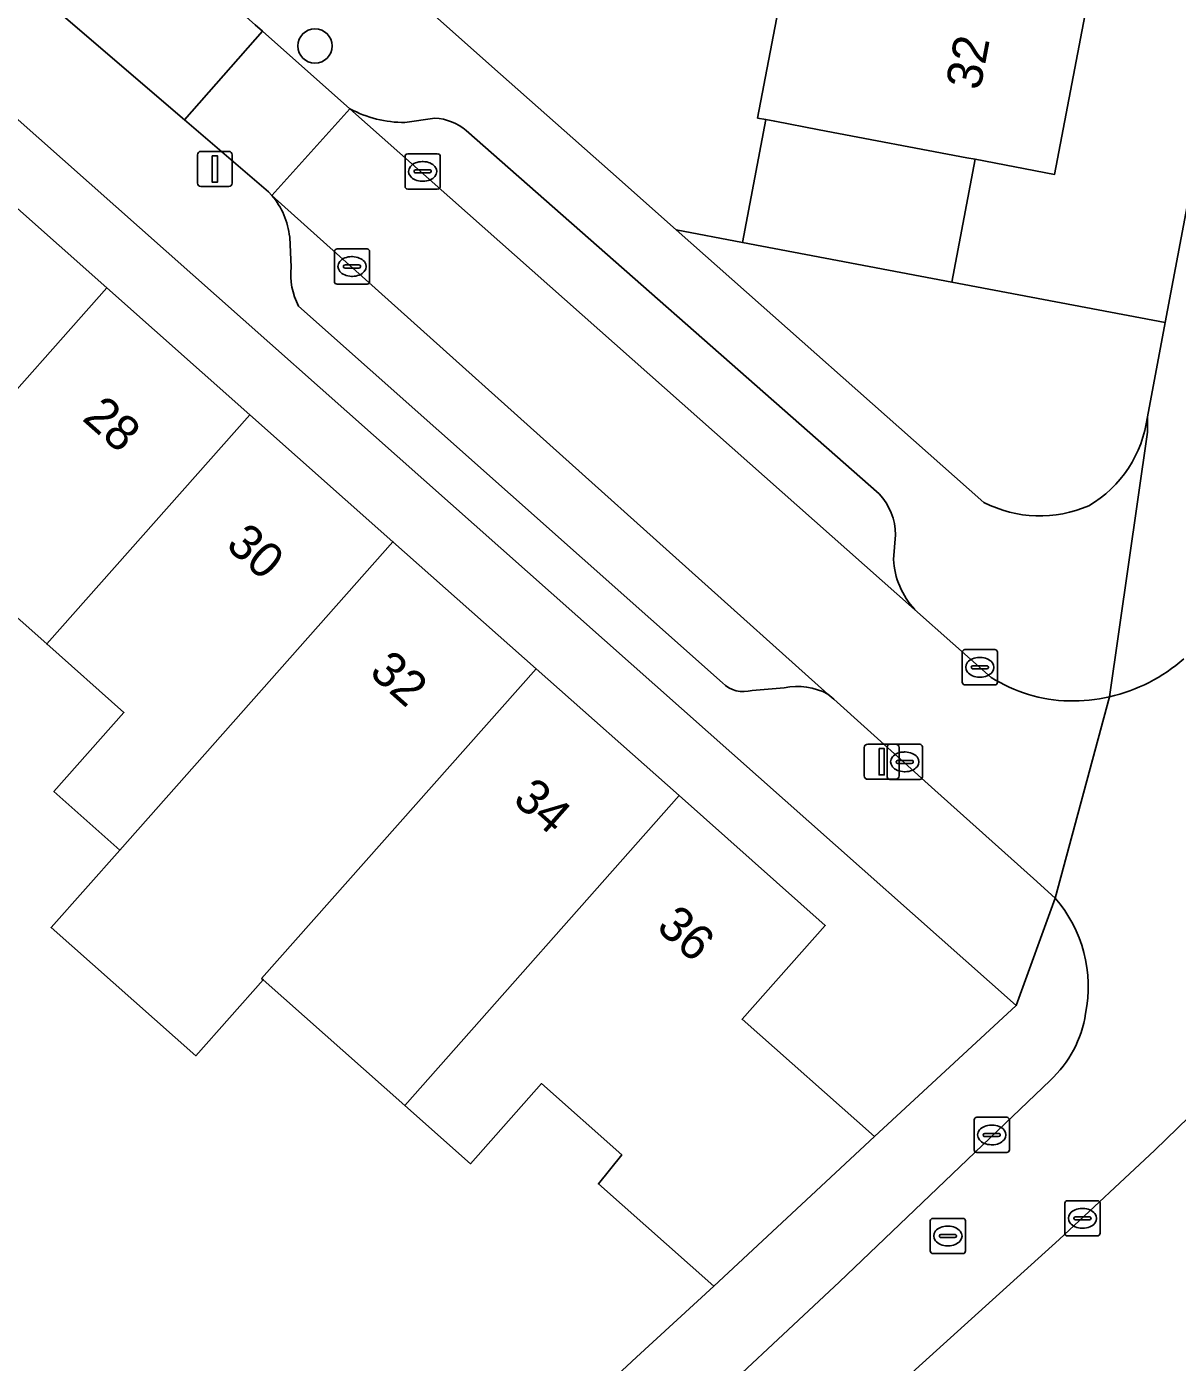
# Model space of a CAD drawing. Extents: x 163147 to 163550, y 380933 to 381639.
# Drawn here: x 163402.15 to 163434.83, y 381022.1 to 381060.03 of the extents above; entities that cross this region are included whole.
import ezdxf

# ---------------------------------------------------------------- set-up
doc = ezdxf.new("R2010")
doc.units = 0
for name, color, linetype in [('IMGEO_Boom', 7, 'Continuous'), ('IMGEO_Erf', 7, 'Continuous'), ('IMGEO_Groenvoorziening', 7, 'Continuous'), ('IMGEO_Kolk', 7, 'Continuous'), ('IMGEO_Lichtmast', 7, 'Continuous'), ('IMGEO_Muur', 7, 'Continuous'), ('IMGEO_Pand', 7, 'Continuous'), ('IMGEO_Pand_nummerreeks', 7, 'Continuous'), ('IMGEO_Parkeervlak_open', 7, 'Continuous'), ('IMGEO_Rijbaan_lokaal_open', 7, 'Continuous'), ('IMGEO_Rioolput', 7, 'Continuous'), ('IMGEO_Voetpad_open', 7, 'Continuous')]:
    doc.layers.add(name, color=color, linetype=linetype)

msp = doc.modelspace()

# ---------------------------------------------------------------- linework, layer by layer
at = {"layer": 'IMGEO_Boom'}
msp.add_circle((163410.34, 381059.48), 0.489, dxfattribs=at)
at = {"layer": 'IMGEO_Erf'}
for points in [[(163380.041, 381074.245), (163384.106, 381070.638), (163388.17, 381067.033), (163392.234, 381063.427), (163396.298, 381059.822), (163400.361, 381056.217), (163404.425, 381052.611), (163408.489, 381049.006), (163412.553, 381045.4), (163416.617, 381041.795), (163420.681, 381038.189), (163424.834, 381034.505), (163422.47, 381031.841), (163426.228, 381028.508), (163430.25, 381032.233), (163348.313, 381104.939)], [(163435.463, 381077.499), (163434.445, 381072.144), (163433.428, 381066.79), (163432.41, 381061.436), (163431.345, 381055.832), (163429.088, 381056.261), (163428.425, 381052.773), (163434.486, 381051.622), (163441.105, 381086.644)], [(163413.645, 381060.421), (163415.366, 381058.896), (163418.735, 381055.912), (163420.6, 381054.259), (163422.486, 381053.901), (163423.149, 381057.389), (163422.91, 381057.434), (163423.49, 381060.487)], [(163405.039, 381008.81), (163419.469, 381022.239), (163421.663, 381024.258), (163418.388, 381027.163), (163419.053, 381027.989), (163416.776, 381030.012), (163414.756, 381027.733), (163412.887, 381029.393), (163408.87, 381032.959), (163406.956, 381030.801), (163402.846, 381034.445), (163404.794, 381036.643), (163402.925, 381038.304), (163404.915, 381040.549), (163402.722, 381042.497), (163400.529, 381044.445)]]:
    msp.add_lwpolyline(points, dxfattribs=at)
at = {"layer": 'IMGEO_Groenvoorziening'}
for points in [[(163434.486, 381051.622), (163428.425, 381052.773), (163422.486, 381053.901), (163420.6, 381054.259), (163429.339, 381046.517)], [(163433.981, 381048.948), (163434.486, 381051.622)]]:
    msp.add_lwpolyline(points, dxfattribs=at)
for centre, radius, start, end in [((163430.589, 381049.373), 3.418, 300.322, 352.8651), ((163430.928, 381049.622), 3.488, 242.9053, 293.4379)]:
    msp.add_arc(centre, radius, start, end, dxfattribs=at)
at = {"layer": 'IMGEO_Kolk'}
for p, q in [((163412.897, 381055.49), (163412.897, 381056.342)), ((163412.972, 381056.416), (163413.824, 381056.416)), ((163413.898, 381056.342), (163413.898, 381055.49)), ((163413.156, 381055.91), (163413.156, 381055.922)), ((163413.594, 381055.873), (163413.196, 381055.873)), ((163413.199, 381055.959), (163413.597, 381055.959)), ((163413.385, 381056.196), (163413.41, 381056.196)), ((163413.64, 381055.922), (163413.64, 381055.91)), ((163413.408, 381055.636), (163413.383, 381055.636)), ((163413.824, 381055.416), (163412.972, 381055.416)), ((163410.891, 381052.791), (163410.891, 381053.643)), ((163410.966, 381053.717), (163411.818, 381053.717)), ((163411.892, 381053.643), (163411.892, 381052.791)), ((163411.15, 381053.211), (163411.15, 381053.223)), ((163411.193, 381053.26), (163411.591, 381053.26)), ((163411.379, 381053.497), (163411.404, 381053.497)), ((163411.634, 381053.223), (163411.634, 381053.211)), ((163411.588, 381053.174), (163411.19, 381053.174)), ((163411.402, 381052.937), (163411.377, 381052.937)), ((163411.818, 381052.717), (163410.966, 381052.717)), ((163428.722, 381041.409), (163428.722, 381042.261)), ((163428.797, 381042.335), (163429.649, 381042.335)), ((163429.723, 381042.261), (163429.723, 381041.409)), ((163428.981, 381041.829), (163428.981, 381041.841)), ((163429.024, 381041.878), (163429.422, 381041.878)), ((163429.21, 381042.115), (163429.235, 381042.115)), ((163429.465, 381041.841), (163429.465, 381041.829)), ((163429.419, 381041.792), (163429.021, 381041.792)), ((163429.233, 381041.555), (163429.208, 381041.555)), ((163429.649, 381041.335), (163428.797, 381041.335)), ((163426.589, 381038.723), (163426.589, 381039.575)), ((163426.664, 381039.649), (163427.516, 381039.649)), ((163427.59, 381039.575), (163427.59, 381038.723)), ((163426.891, 381039.192), (163427.289, 381039.192)), ((163427.077, 381039.429), (163427.102, 381039.429)), ((163426.848, 381039.143), (163426.848, 381039.155)), ((163427.286, 381039.106), (163426.888, 381039.106)), ((163427.1, 381038.869), (163427.075, 381038.869)), ((163427.332, 381039.155), (163427.332, 381039.143)), ((163427.516, 381038.649), (163426.664, 381038.649)), ((163429.06, 381028.128), (163429.06, 381028.98)), ((163429.135, 381029.054), (163429.987, 381029.054)), ((163430.061, 381028.98), (163430.061, 381028.128)), ((163429.319, 381028.548), (163429.319, 381028.56)), ((163429.362, 381028.597), (163429.76, 381028.597)), ((163429.548, 381028.834), (163429.573, 381028.834)), ((163429.803, 381028.56), (163429.803, 381028.548)), ((163429.757, 381028.511), (163429.359, 381028.511)), ((163429.571, 381028.274), (163429.546, 381028.274)), ((163429.987, 381028.054), (163429.135, 381028.054)), ((163431.712, 381026.685), (163432.564, 381026.685)), ((163431.637, 381025.759), (163431.637, 381026.611)), ((163432.125, 381026.465), (163432.15, 381026.465)), ((163432.638, 381026.611), (163432.638, 381025.759)), ((163431.896, 381026.179), (163431.896, 381026.191)), ((163432.334, 381026.142), (163431.936, 381026.142)), ((163431.939, 381026.228), (163432.337, 381026.228)), ((163432.148, 381025.905), (163432.123, 381025.905)), ((163432.38, 381026.191), (163432.38, 381026.179)), ((163432.564, 381025.685), (163431.712, 381025.685))]:
    msp.add_line(p, q, dxfattribs=at)
for points in [[(163412.897, 381055.49), (163412.897, 381056.342)], [(163412.972, 381056.416), (163413.824, 381056.416)], [(163413.898, 381056.342), (163413.898, 381055.49)], [(163413.824, 381055.416), (163412.972, 381055.416)], [(163410.891, 381052.791), (163410.891, 381053.643)], [(163410.966, 381053.717), (163411.818, 381053.717)], [(163411.892, 381053.643), (163411.892, 381052.791)], [(163411.818, 381052.717), (163410.966, 381052.717)], [(163428.722, 381041.409), (163428.722, 381042.261)], [(163428.797, 381042.335), (163429.649, 381042.335)], [(163429.723, 381042.261), (163429.723, 381041.409)], [(163429.649, 381041.335), (163428.797, 381041.335)], [(163426.589, 381038.723), (163426.589, 381039.575)], [(163426.664, 381039.649), (163427.516, 381039.649)], [(163427.59, 381039.575), (163427.59, 381038.723)], [(163427.516, 381038.649), (163426.664, 381038.649)], [(163429.06, 381028.128), (163429.06, 381028.98)], [(163429.135, 381029.054), (163429.987, 381029.054)], [(163430.061, 381028.98), (163430.061, 381028.128)], [(163429.987, 381028.054), (163429.135, 381028.054)], [(163431.712, 381026.685), (163432.564, 381026.685)], [(163431.637, 381025.759), (163431.637, 381026.611)], [(163432.638, 381026.611), (163432.638, 381025.759)], [(163432.564, 381025.685), (163431.712, 381025.685)]]:
    msp.add_lwpolyline(points, dxfattribs=at)
for centre, radius, start, end in [((163412.974, 381056.34), 0.0765, 91.552, 178.448), ((163412.974, 381056.34), 0.0765, 91.552, 178.448), ((163413.822, 381056.34), 0.0765, 1.552, 88.448), ((163413.822, 381056.34), 0.0765, 1.552, 88.448), ((163413.196, 381055.919), 0.0403, 85.8775, 175.7526), ((163413.193, 381055.909), 0.0366, 178.938, 274.7102), ((163413.597, 381055.916), 0.043, 264.8664, 352.4533), ((163413.601, 381055.921), 0.0386, 1.7309, 96.639), ((163412.974, 381055.492), 0.0765, 181.552, 268.448), ((163412.974, 381055.492), 0.0765, 181.552, 268.448), ((163413.822, 381055.492), 0.0765, 271.552, 358.448), ((163413.822, 381055.492), 0.0765, 271.552, 358.448), ((163410.968, 381053.641), 0.0765, 91.552, 178.448), ((163410.968, 381053.641), 0.0765, 91.552, 178.448), ((163411.816, 381053.641), 0.0765, 1.552, 88.448), ((163411.816, 381053.641), 0.0765, 1.552, 88.448), ((163411.19, 381053.22), 0.0403, 85.8775, 175.7526), ((163411.187, 381053.21), 0.0366, 178.938, 274.7102), ((163411.591, 381053.217), 0.043, 264.8664, 352.4533), ((163411.595, 381053.222), 0.0386, 1.7309, 96.639), ((163410.968, 381052.793), 0.0765, 181.552, 268.448), ((163410.968, 381052.793), 0.0765, 181.552, 268.448), ((163411.816, 381052.793), 0.0765, 271.552, 358.448), ((163411.816, 381052.793), 0.0765, 271.552, 358.448), ((163428.799, 381042.259), 0.0765, 91.552, 178.448), ((163428.799, 381042.259), 0.0765, 91.552, 178.448), ((163429.647, 381042.259), 0.0765, 1.552, 88.448), ((163429.647, 381042.259), 0.0765, 1.552, 88.448), ((163429.021, 381041.838), 0.0403, 85.8775, 175.7526), ((163429.426, 381041.84), 0.0386, 1.7309, 96.639), ((163429.018, 381041.828), 0.0366, 178.938, 274.7102), ((163429.422, 381041.835), 0.043, 264.8664, 352.4533), ((163428.799, 381041.411), 0.0765, 181.552, 268.448), ((163428.799, 381041.411), 0.0765, 181.552, 268.448), ((163429.647, 381041.411), 0.0765, 271.552, 358.448), ((163429.647, 381041.411), 0.0765, 271.552, 358.448), ((163426.666, 381039.573), 0.0765, 91.552, 178.448), ((163426.666, 381039.573), 0.0765, 91.552, 178.448), ((163427.514, 381039.573), 0.0765, 1.552, 88.448), ((163427.514, 381039.573), 0.0765, 1.552, 88.448), ((163426.888, 381039.152), 0.0403, 85.8775, 175.7526), ((163427.293, 381039.154), 0.0386, 1.7309, 96.639), ((163426.885, 381039.142), 0.0366, 178.938, 274.7102), ((163427.289, 381039.149), 0.043, 264.8664, 352.4533), ((163426.666, 381038.725), 0.0765, 181.552, 268.448), ((163426.666, 381038.725), 0.0765, 181.552, 268.448), ((163427.514, 381038.725), 0.0765, 271.552, 358.448), ((163427.514, 381038.725), 0.0765, 271.552, 358.448), ((163429.137, 381028.978), 0.0765, 91.552, 178.448), ((163429.137, 381028.978), 0.0765, 91.552, 178.448), ((163429.985, 381028.978), 0.0765, 1.552, 88.448), ((163429.985, 381028.978), 0.0765, 1.552, 88.448), ((163429.359, 381028.557), 0.0403, 85.8775, 175.7526), ((163429.764, 381028.559), 0.0386, 1.7309, 96.639), ((163429.356, 381028.547), 0.0366, 178.938, 274.7102), ((163429.76, 381028.554), 0.043, 264.8664, 352.4533), ((163429.137, 381028.13), 0.0765, 181.552, 268.448), ((163429.137, 381028.13), 0.0765, 181.552, 268.448), ((163429.985, 381028.13), 0.0765, 271.552, 358.448), ((163429.985, 381028.13), 0.0765, 271.552, 358.448), ((163431.714, 381026.609), 0.0765, 91.552, 178.448), ((163431.714, 381026.609), 0.0765, 91.552, 178.448), ((163432.562, 381026.609), 0.0765, 1.552, 88.448), ((163432.562, 381026.609), 0.0765, 1.552, 88.448), ((163431.936, 381026.188), 0.0403, 85.8775, 175.7526), ((163431.933, 381026.178), 0.0366, 178.938, 274.7102), ((163432.337, 381026.185), 0.043, 264.8664, 352.4533), ((163432.341, 381026.19), 0.0386, 1.7309, 96.639), ((163431.714, 381025.761), 0.0765, 181.552, 268.448), ((163431.714, 381025.761), 0.0765, 181.552, 268.448), ((163432.562, 381025.761), 0.0765, 271.552, 358.448), ((163432.562, 381025.761), 0.0765, 271.552, 358.448)]:
    msp.add_arc(centre, radius, start, end, dxfattribs=at)
for centre, major_axis, ratio, start_param, end_param in [((163413.384, 381055.916), (-0.387, 0.002), 0.722429, 4.712389, 7.853982), ((163413.409, 381055.916), (-0.39, 0.002), 0.717154, 1.570796, 4.712389), ((163411.378, 381053.217), (-0.387, 0.002), 0.722429, 4.712389, 7.853982), ((163411.403, 381053.217), (-0.39, 0.002), 0.717154, 1.570796, 4.712389), ((163429.209, 381041.835), (-0.387, 0.002), 0.722429, 4.712389, 7.853982), ((163429.234, 381041.835), (-0.39, 0.002), 0.717154, 1.570796, 4.712389), ((163427.076, 381039.149), (-0.387, 0.002), 0.722429, 4.712389, 7.853982), ((163427.101, 381039.149), (-0.39, 0.002), 0.717154, 1.570796, 4.712389), ((163429.547, 381028.554), (-0.387, 0.002), 0.722429, 4.712389, 7.853982), ((163429.572, 381028.554), (-0.39, 0.002), 0.717154, 1.570796, 4.712389), ((163432.124, 381026.185), (-0.387, 0.002), 0.722429, 4.712389, 7.853982), ((163432.149, 381026.185), (-0.39, 0.002), 0.717154, 1.570796, 4.712389)]:
    msp.add_ellipse(centre, major_axis=major_axis, ratio=ratio, start_param=start_param, end_param=end_param, dxfattribs=at)
at = {"layer": 'IMGEO_Lichtmast'}
for p, q in [((163407, 381055.587), (163407, 381056.387)), ((163407, 381056.387), (163407, 381055.587)), ((163407.1, 381056.487), (163407.89, 381056.487)), ((163407.89, 381056.487), (163407.1, 381056.487)), ((163407.99, 381056.387), (163407.99, 381055.587)), ((163407.99, 381055.587), (163407.99, 381056.387)), ((163407.89, 381055.487), (163407.1, 381055.487)), ((163407.1, 381055.487), (163407.89, 381055.487)), ((163426.039, 381039.653), (163426.829, 381039.653)), ((163426.829, 381039.653), (163426.039, 381039.653)), ((163425.939, 381038.753), (163425.939, 381039.553)), ((163425.939, 381039.553), (163425.939, 381038.753)), ((163426.929, 381039.553), (163426.929, 381038.753)), ((163426.929, 381038.753), (163426.929, 381039.553)), ((163426.829, 381038.653), (163426.039, 381038.653)), ((163426.039, 381038.653), (163426.829, 381038.653))]:
    msp.add_line(p, q, dxfattribs=at)
for points in [[(163407.42, 381056.362), (163407.57, 381056.362), (163407.57, 381055.612), (163407.42, 381055.612), (163407.42, 381056.362)], [(163426.359, 381039.528), (163426.509, 381039.528), (163426.509, 381038.778), (163426.359, 381038.778), (163426.359, 381039.528)]]:
    msp.add_lwpolyline(points, dxfattribs=at)
for centre, start, end in [((163407.1, 381056.387), 90, 180), ((163407.1, 381056.387), 90, 180), ((163407.89, 381056.387), 0, 90), ((163407.89, 381056.387), 360, 90), ((163407.1, 381055.587), 180, 270), ((163407.1, 381055.587), 180, 270), ((163407.89, 381055.587), 270, 0), ((163407.89, 381055.587), 270, 0), ((163426.039, 381039.553), 90, 180), ((163426.039, 381039.553), 90, 180), ((163426.829, 381039.553), 0, 90), ((163426.829, 381039.553), 360, 90), ((163426.039, 381038.753), 180, 270), ((163426.039, 381038.753), 180, 270), ((163426.829, 381038.753), 270, 0), ((163426.829, 381038.753), 270, 0)]:
    msp.add_arc(centre, 0.1, start, end, dxfattribs=at)
at = {"layer": 'IMGEO_Muur'}
for points in [[(163415.366, 381058.896), (163418.735, 381055.912)], [(163419.469, 381022.239), (163421.663, 381024.258)]]:
    msp.add_lwpolyline(points, dxfattribs=at)
at = {"layer": 'IMGEO_Pand'}
for points in [[(163432.41, 381061.436), (163421.267, 381063.548), (163420.61, 381063.673), (163420.127, 381061.126), (163420.81, 381060.996), (163423.49, 381060.487), (163422.91, 381057.434), (163423.149, 381057.389), (163423.398, 381057.341), (163424.655, 381057.103), (163428.856, 381056.305), (163429.088, 381056.261), (163431.345, 381055.832)], [(163429.088, 381056.261), (163428.856, 381056.305), (163424.655, 381057.103), (163423.398, 381057.341), (163423.149, 381057.389), (163422.486, 381053.901), (163428.425, 381052.773)], [(163404.425, 381052.611), (163400.361, 381056.217), (163394.598, 381049.713), (163396.791, 381047.766), (163394.801, 381045.52), (163396.671, 381043.86)], [(163408.489, 381049.006), (163404.425, 381052.611), (163396.671, 381043.86), (163398.539, 381042.2), (163400.529, 381044.445), (163402.722, 381042.497)], [(163408.489, 381049.006), (163402.722, 381042.497), (163404.915, 381040.549), (163402.925, 381038.304), (163404.794, 381036.643), (163412.553, 381045.4)], [(163416.617, 381041.795), (163412.553, 381045.4), (163404.794, 381036.643), (163402.846, 381034.445), (163406.956, 381030.801), (163408.87, 381032.959), (163408.824, 381032.999)], [(163420.681, 381038.189), (163416.617, 381041.795), (163408.824, 381032.999), (163408.87, 381032.959), (163412.887, 381029.393)], [(163412.887, 381029.393), (163414.756, 381027.733), (163416.776, 381030.012), (163419.053, 381027.989), (163418.388, 381027.163), (163421.663, 381024.258), (163426.228, 381028.508), (163422.47, 381031.841), (163424.834, 381034.505), (163420.681, 381038.189)]]:
    msp.add_lwpolyline(points, close=True, dxfattribs=at)
at = {"layer": 'IMGEO_Parkeervlak_open'}
for points in [[(163411.331, 381057.699), (163427.371, 381043.474)], [(163413.748, 381057.432), (163412.895, 381057.305)], [(163426.365, 381046.76), (163414.631, 381057.076)], [(163424.908, 381041.074), (163409.114, 381055.234)], [(163409.621, 381054.053), (163409.659, 381053.202)], [(163409.872, 381052.094), (163421.917, 381041.392)], [(163426.769, 381044.9), (163426.83, 381045.598)], [(163422.752, 381041.177), (163423.667, 381041.252)]]:
    msp.add_lwpolyline(points, dxfattribs=at)
for centre, radius, start, end in [((163412.9, 381060.625), 3.32, 241.802, 269.9187), ((163413.65, 381055.916), 1.519, 49.7815, 86.3028), ((163407.465, 381053.827), 2.168, 5.9913, 40.4761), ((163411.657, 381053.012), 2.007, 174.5597, 207.2037), ((163425.081, 381045.572), 1.749, 0.8458, 42.774), ((163429.075, 381045.033), 2.309, 183.3078, 222.4673), ((163422.516, 381041.988), 0.845, 224.887, 286.2347), ((163424.037, 381039.418), 1.871, 62.2658, 101.4093)]:
    msp.add_arc(centre, radius, start, end, dxfattribs=at)
at = {"layer": 'IMGEO_Rijbaan_lokaal_open'}
for points in [[(163384.971, 381081.074), (163384.78, 381081.243), (163378.55, 381086.767), (163376.265, 381084.191), (163386.023, 381075.538), (163387.932, 381073.845), (163402.686, 381060.759), (163402.997, 381060.496), (163406.637, 381057.379), (163408.848, 381059.9), (163408.639, 381060.085), (163389.921, 381076.681), (163388.332, 381078.092)], [(163411.331, 381057.699), (163408.848, 381059.9), (163406.637, 381057.379), (163409.019, 381055.339), (163409.114, 381055.234)]]:
    msp.add_lwpolyline(points, close=True, dxfattribs=at)
for points in [[(163411.331, 381057.699), (163409.114, 381055.234), (163424.908, 381041.074), (163425.074, 381040.927), (163427.947, 381038.346), (163430.742, 381035.835), (163431.364, 381035.276), (163432.904, 381040.995)], [(163429.543, 381041.548), (163427.371, 381043.474), (163411.331, 381057.699)], [(163425.737, 381020.394), (163426.096, 381020.718), (163431.477, 381025.583), (163434.189, 381028.125), (163436.759, 381030.613), (163438.315, 381039.154), (163438.371, 381039.461), (163438.435, 381039.8), (163439.15, 381043.603), (163436.035, 381044.203), (163435.931, 381043.816)], [(163432.904, 381040.995), (163431.364, 381035.276)], [(163431.22, 381030.101), (163425.239, 381024.377), (163407.169, 381007.491), (163409.269, 381005.247), (163409.794, 381005.73), (163425.737, 381020.394)]]:
    msp.add_lwpolyline(points, dxfattribs=at)
for centre, radius, start, end in [((163431.856, 381045.641), 4.762, 282.7183, 311.5777), ((163431.86, 381045.217), 4.34, 237.7284, 268.5592), ((163431.852, 381045.668), 4.79, 268.797, 282.6931), ((163428.485, 381032.768), 3.818, 348.3794, 41.063), ((163429.003, 381032.49), 3.259, 312.8594, 351.3378)]:
    msp.add_arc(centre, radius, start, end, dxfattribs=at)
at = {"layer": 'IMGEO_Rioolput'}
for p, q in [((163427.814, 381025.258), (163427.814, 381026.11)), ((163427.889, 381026.184), (163428.741, 381026.184)), ((163428.302, 381025.964), (163428.327, 381025.964)), ((163428.815, 381026.11), (163428.815, 381025.258)), ((163428.073, 381025.678), (163428.073, 381025.69)), ((163428.511, 381025.641), (163428.113, 381025.641)), ((163428.116, 381025.727), (163428.514, 381025.727)), ((163428.557, 381025.69), (163428.557, 381025.678)), ((163428.741, 381025.184), (163427.889, 381025.184)), ((163428.325, 381025.404), (163428.3, 381025.404))]:
    msp.add_line(p, q, dxfattribs=at)
for points in [[(163427.814, 381025.258), (163427.814, 381026.11)], [(163427.889, 381026.184), (163428.741, 381026.184)], [(163428.815, 381026.11), (163428.815, 381025.258)], [(163428.741, 381025.184), (163427.889, 381025.184)]]:
    msp.add_lwpolyline(points, dxfattribs=at)
for centre, radius, start, end in [((163427.891, 381026.108), 0.0765, 91.552, 178.448), ((163427.891, 381026.108), 0.0765, 91.552, 178.448), ((163428.739, 381026.108), 0.0765, 1.552, 88.448), ((163428.739, 381026.108), 0.0765, 1.552, 88.448), ((163428.113, 381025.687), 0.0403, 85.8775, 175.7526), ((163428.11, 381025.677), 0.0366, 178.938, 274.7102), ((163428.514, 381025.684), 0.043, 264.8664, 352.4533), ((163428.518, 381025.689), 0.0386, 1.7309, 96.639), ((163427.891, 381025.26), 0.0765, 181.552, 268.448), ((163427.891, 381025.26), 0.0765, 181.552, 268.448), ((163428.739, 381025.26), 0.0765, 271.552, 358.448), ((163428.739, 381025.26), 0.0765, 271.552, 358.448)]:
    msp.add_arc(centre, radius, start, end, dxfattribs=at)
for centre, major_axis, ratio, start_param, end_param in [((163428.301, 381025.684), (-0.387, 0.002), 0.722429, 4.712389, 7.853982), ((163428.326, 381025.684), (-0.39, 0.002), 0.717154, 1.570796, 4.712389)]:
    msp.add_ellipse(centre, major_axis=major_axis, ratio=ratio, start_param=start_param, end_param=end_param, dxfattribs=at)
at = {"layer": 'IMGEO_Voetpad_open'}
for points in [[(163429.339, 381046.517), (163420.6, 381054.259), (163418.735, 381055.912), (163415.366, 381058.896), (163413.645, 381060.421), (163412.679, 381061.277), (163348.475, 381118.157)], [(163354.767, 381103.254), (163351.292, 381106.335), (163348.313, 381104.939), (163430.25, 381032.233), (163431.364, 381035.276), (163430.742, 381035.835), (163427.947, 381038.346), (163425.074, 381040.927), (163424.908, 381041.074)], [(163441.105, 381086.644), (163434.486, 381051.622), (163433.981, 381048.948), (163433.984, 381048.514), (163432.904, 381040.995)], [(163409.114, 381055.234), (163409.019, 381055.339), (163406.637, 381057.379), (163402.997, 381060.496), (163402.686, 381060.759)], [(163408.639, 381060.085), (163408.848, 381059.9), (163411.331, 381057.699)], [(163412.895, 381057.305), (163413.748, 381057.432)], [(163414.631, 381057.076), (163426.365, 381046.76)], [(163409.659, 381053.202), (163409.621, 381054.053)], [(163421.917, 381041.392), (163409.872, 381052.094)], [(163432.904, 381040.995), (163433.984, 381048.514), (163433.981, 381048.948)], [(163426.83, 381045.598), (163426.769, 381044.9)], [(163427.371, 381043.474), (163429.543, 381041.548)], [(163423.667, 381041.252), (163422.752, 381041.177)], [(163431.364, 381035.276), (163430.25, 381032.233), (163426.228, 381028.508), (163421.663, 381024.258), (163419.469, 381022.239), (163405.039, 381008.81), (163404.04, 381007.881), (163403.875, 381007.733), (163395.261, 381000), (163385.833, 380991.536), (163387.473, 380989.102), (163399.16, 381000), (163403.774, 381004.316), (163404.768, 381005.246), (163407.169, 381007.491), (163425.239, 381024.377), (163431.22, 381030.101)], [(163438.452, 381031.953), (163436.759, 381030.613), (163434.189, 381028.125), (163431.477, 381025.583), (163426.096, 381020.718), (163425.737, 381020.394)]]:
    msp.add_lwpolyline(points, dxfattribs=at)
for centre, radius, start, end in [((163412.9, 381060.625), 3.32, 241.802, 269.9187), ((163413.65, 381055.916), 1.519, 49.7815, 86.3028), ((163407.465, 381053.827), 2.168, 5.9913, 40.4761), ((163411.657, 381053.012), 2.007, 174.5597, 207.2037), ((163430.589, 381049.373), 3.418, 300.322, 352.8651), ((163425.081, 381045.572), 1.749, 0.8458, 42.774), ((163430.928, 381049.622), 3.488, 242.9053, 293.4379), ((163429.075, 381045.033), 2.309, 183.3078, 222.4673), ((163431.856, 381045.641), 4.762, 282.7183, 311.5777), ((163431.86, 381045.217), 4.34, 237.7284, 268.5592), ((163422.516, 381041.988), 0.845, 224.887, 286.2347), ((163424.037, 381039.418), 1.871, 62.2658, 101.4093), ((163431.852, 381045.668), 4.79, 268.797, 282.6931), ((163428.485, 381032.768), 3.818, 348.3794, 41.063), ((163429.003, 381032.49), 3.259, 312.8594, 351.3378)]:
    msp.add_arc(centre, radius, start, end, dxfattribs=at)

# ---------------------------------------------------------------- texts
at = {"layer": 'IMGEO_Pand_nummerreeks'}
for s, rotation, p in [('32', 79.2401, (163429.23, 381058.197)), ('28', 318.4212, (163403.697, 381048.873)), ('30', 318.4212, (163407.773, 381045.256)), ('32', 318.4205, (163411.846, 381041.643)), ('34', 318.4205, (163415.924, 381038.025)), ('36', 318.4212, (163420.001, 381034.408))]:
    msp.add_text(s, height=1, rotation=rotation, dxfattribs=at).set_placement(p)

doc.saveas('drawing.dxf')
